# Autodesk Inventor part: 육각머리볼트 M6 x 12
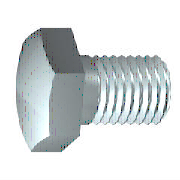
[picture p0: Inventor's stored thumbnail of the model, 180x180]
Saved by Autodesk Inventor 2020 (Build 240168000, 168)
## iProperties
IsCustomPart: 1
Created: 2012-02
Part Number: 육각머리볼트 M6 x 12
Material: 스테인리스강
Description: 6각 머리 나사
Document SubType Name: Modeling
Standard: ISO 4017
Designer: mdu-01
Standard Revision: Third edition 1999-08-15
Standards Organization: ISO
Language: ko-KR
Size Designation: M6 x 12
Categories: <MemberInstance><Categories><Category DisplayName="조임쇠" InternalName="e4da775c-781d-43d5-af7c-5136215cf5a6" Mnemonic="FSTN"><Category DisplayName="볼트" InternalN
Density: 7.75 g/cm^3
Appearance: 반광택
Author: mdu-01
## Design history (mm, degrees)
sketch "스케치1"
  geometry: L1 (0, 4.44)-(0, 3); L2 (1.15, 3)-(12, 3); L3 (12, 3)-(12, 0); L4 (12, 0)-(-0.5, 0); L5 (-3, 0)-(14.5, 0) reference; L6 (-0.5, 0)-(-0.5, 4.44); L7 (-0.5, 4.44)-(0, 4.44); L8 (1.15, 3)-(0.536, 3); L9 (0.536, 3)-(0, 3); L10 (0, -0.888)-(0, 5.328) reference
  constraints: 16 end point, 2 collinear, 2 perpendicular, 1 parallel
  dimensions: "d0" = 12 distance between parallel lines of L3 L1 (= NLG); "d1" = 10.85 distance from line of L2.start L3 (= GEL); "d2" = 6 diameter of L2 L4 (= GD); "d9" = 0.5001 distance between parallel lines of L6 L1 (computed from SD); "d10" = 8.88 diameter of L7 L4 (= SD2); "d13" = 0.61355 distance of L2.start L8.end (computed from GAL); "d14" = 6 diameter of L9 L4 (= BDM)
revolve "본체" sketch "스케치1" stored, may be unused: angle "d12" = 90 deg
sketch "스케치2"
  geometry: L1 (0, 5.774)-(5, 2.887); L2 (5, 2.887)-(5, -2.887); L3 (5, -2.887)-(0, -5.774); L4 (0, -5.774)-(-5, -2.887); L5 (-5, -2.887)-(-5, 2.887); L6 (-5, 2.887)-(0, 5.774); 2 further points
  constraints: 12 end point, 1 coincident, 1 vertical, 11 other
  dimensions: "d11" = 10 distance between parallel lines of L5 L2 (= SW)
extrude "머리" join sketch "스케치2" distance "d3" = 3.5 (= KOH - SD); taper "d4" = 0 deg
sketch "스케치4"
  geometry: L1 (-4, 5)-(-4, 5.774); L2 (-4, 5.774)-(-3.554, 5.774); L3 (-3.554, 5.774)-(-4, 5); L4 (-4.7, 0)-(0.2, 0) reference; L5 (-0.5, 5.774)-(-4, 5.774) reference; L6 (-4, 2.887)-(-4, 5.774) reference
  constraints: 6 end point, 2 collinear, 1 perpendicular, 1 vertical
  dimensions: "d5" = 30 deg angle of L3 L1 (= ANG1); "d19" = 10 diameter of L1.start L4 (= SW0)
revolve "모따기1" sketch "스케치4" stored, may be unused: angle "d21" = 90 deg
workplane "Work Plane1"
body "Solid1"
feature "스레드" dims "d15" = 10.85 (= GEL), "d16" = 0
chamfer "모따기2" distance "d6" = 0.61345 (= -0.5 x SPD + 0.5 x GD); stored, may be unused: second distance "d7" = 0.61355 (computed from GUL), angle "d55" = 45 deg
other parameters: "NLG" = 12 [user parameter; used in 1 equation term], "GD" = 6 (= NND) [user parameter; used in 2 equation terms], "BDM" = 6 (= NND) [user parameter; used in 1 equation term], "KOH" = 4 [user parameter; used in 1 equation term], "GEL" = 10.85 [user parameter; used in 2 equation terms], "SW" = 10 [user parameter; used in 2 equation terms], "SW0" = 10 (= SW) [user parameter; used in 1 equation term], "SPD" = 4.7731 (= NND - 1.2269 x PTC) [user parameter; used in 1 equation term], "SD2" = 8.88 [user parameter; used in 2 equation terms], "SD" = 0.5 [user parameter; used in 2 equation terms], "ANG1" = 30 deg [user parameter; used in 1 equation term], "GAL" = 0.61345 (= 0.61345 x PTC) [user parameter; used in 1 equation term], "GUL" = 0.61345 (= 0.61345 x PTC) [user parameter; used in 1 equation term], "d8" = 0, "RR" = 0.25 [user parameter], "d57" = 0, "d58" = 0, "GD1" = 4.7731 (= THREADDIA - 1.2269 x PTC) [user parameter], "THREADDIA" = 6 [user parameter; used in 1 equation term], "SDH" = 8.88 (= SD2) [user parameter], "SDHG" = 3 [user parameter], "TOA" = 30 deg [user parameter], "PTC" = 1 [user parameter; used in 5 equation terms], "NND" = 6 [user parameter; used in 3 equation terms], "E0" = 11.55 [user parameter]
